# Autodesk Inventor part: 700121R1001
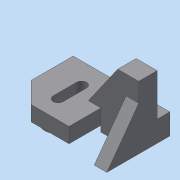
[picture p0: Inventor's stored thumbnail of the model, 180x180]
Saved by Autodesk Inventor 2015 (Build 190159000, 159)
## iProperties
Created: 2020-01
Part Number: 700121R1001
Material: 일반
Document SubType Name: Modeling
Designer: 3DPRINTER
Density: 1 g/cm^3
Appearance: 기본값
Author: 3DPRINTER
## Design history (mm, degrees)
sketch "스케치1"
  geometry: L1 (-35, 53)-(80, 53); L2 (80, 53)-(80, 16); L3 (35, -22)-(-10, -22); L4 (-35, 3)-(-35, 53); L5 (35, -22)-(35, 16); L6 (35, 16)-(80, 16); L7 (65, 16)-(80, 16); L8 (80, 16)-(80, -22); L9 (80, -22)-(65, -22); L10 (65, -22)-(65, 16); L11 (0, 28)-(0, 0); L12 (-6, 28)-(-6, 0); L13 (6, 0)-(6, 28); L14 (-35, 3)-(-10, -22); C1 r 16 at (0, 0); C2 r 10 at (0, 0); A1 r 6 centre (0, 28) between (6, 28) and (-6, 28); A2 r 6 centre (0, 0) between (-6, 0) and (6, 0); 2 further points
  constraints: 30 end point, 5 parallel, 4 centre point, 4 point on circle, 4 tangent, 3 coincident, 2 horizontal, 2 perpendicular, 1 midpoint, 1 vertical
  dimensions: "d0" = 16 radius of C1; "d1" = 10 radius of C2; "d2" = 38 distance between parallel lines of L3 L6; "d3" = 35 horizontal distance of L1.start point (0, 0); "d4" = 53 distance from line of L1 C2.centre; "d5" = 45 distance between parallel lines of L2 L5; "d6" = 115 distance between parallel lines of L2 L4; "d7" = 75 distance between parallel lines of L3 L1; "d8" = 15 distance between parallel lines of L8 L10; "d9" = 38 distance between parallel lines of L9 L7; "d10" = 28 distance of point (0, 0) L11.start; "d11" = 6 radius of A1; "d12" = 25 horizontal distance of L4.start L3.end; "d13" = 45 deg angle of L3 L14
extrude "돌출1" new body sketch "스케치1" distance "d14" = 60; taper "d15" = 0 deg
sketch "스케치2"
  geometry: L1 (0, 0)-(-52.303, 38); L2 (-52.303, 38)-(-60, 38); L3 (0, 38)-(-60, 38) reference; L4 (-60, 38)-(-60, 0); L5 (-60, 0)-(0, 0); L6 (0, 0)-(-60, 0) reference; 1 further point
  constraints: 8 end point, 2 collinear, 1 perpendicular
  dimensions: "d16" = 144 deg angle of L1 L2
extrude "돌출2" cut sketch "스케치2" stored distance "d17" = 60; taper "d18" = 0 deg
extrude "돌출3" join sketch "스케치1" distance "d19" = 25; taper "d20" = 0 deg
sketch "스케치3"
  geometry: L1 (-25, 7)-(45, 7); L2 (45, 7)-(45, 0); L3 (45, 0)-(-25, 0); L4 (-25, 0)-(-25, 7); 2 further points
  constraints: 8 end point, 2 parallel, 1 coincident, 1 horizontal, 1 perpendicular
  dimensions: "d21" = 7 distance between parallel lines of L3 L1; "d22" = 70 distance between parallel lines of L2 L4
extrude "돌출4" cut sketch "스케치3" stored distance "d23" = 25; taper "d24" = 0 deg
extrude "돌출5" join sketch "스케치1" distance "d25" = 7; taper "d26" = 0 deg
sketch "스케치4"
  geometry: L1 (-6, 28)-(-6, 0) reference; L2 (6, 0)-(6, 28) reference; A1 r 6 centre (0, 28) between (6, 28) and (-6, 28) reference; A2 r 6 centre (0, 0) between (-6, 0) and (6, 0) reference; 1 further point
extrude "돌출6" cut sketch "스케치4" distance "d19" = 25; distance "d27" = 12; taper "d28" = 0 deg
sketch "스케치5"
  geometry: L1 (45, 0)-(45, 50); L2 (45, 50)-(20, 50); L3 (20, 50)-(-15.01, 0); L4 (-15.01, 0)-(45, 0); L5 (45, -25)-(0, -25) reference; 3 further points
  constraints: 8 end point, 2 horizontal, 1 coincident, 1 midpoint, 1 vertical
  dimensions: "d29" = 25 distance of L1.end L2.end; "d30" = 55 deg angle of L3 L2; "d32" = 50 distance between parallel lines of L4 L2
extrude "돌출7" join sketch "스케치5" distance "d33" = 22; taper "d34" = 0 deg
node "솔리드1"
